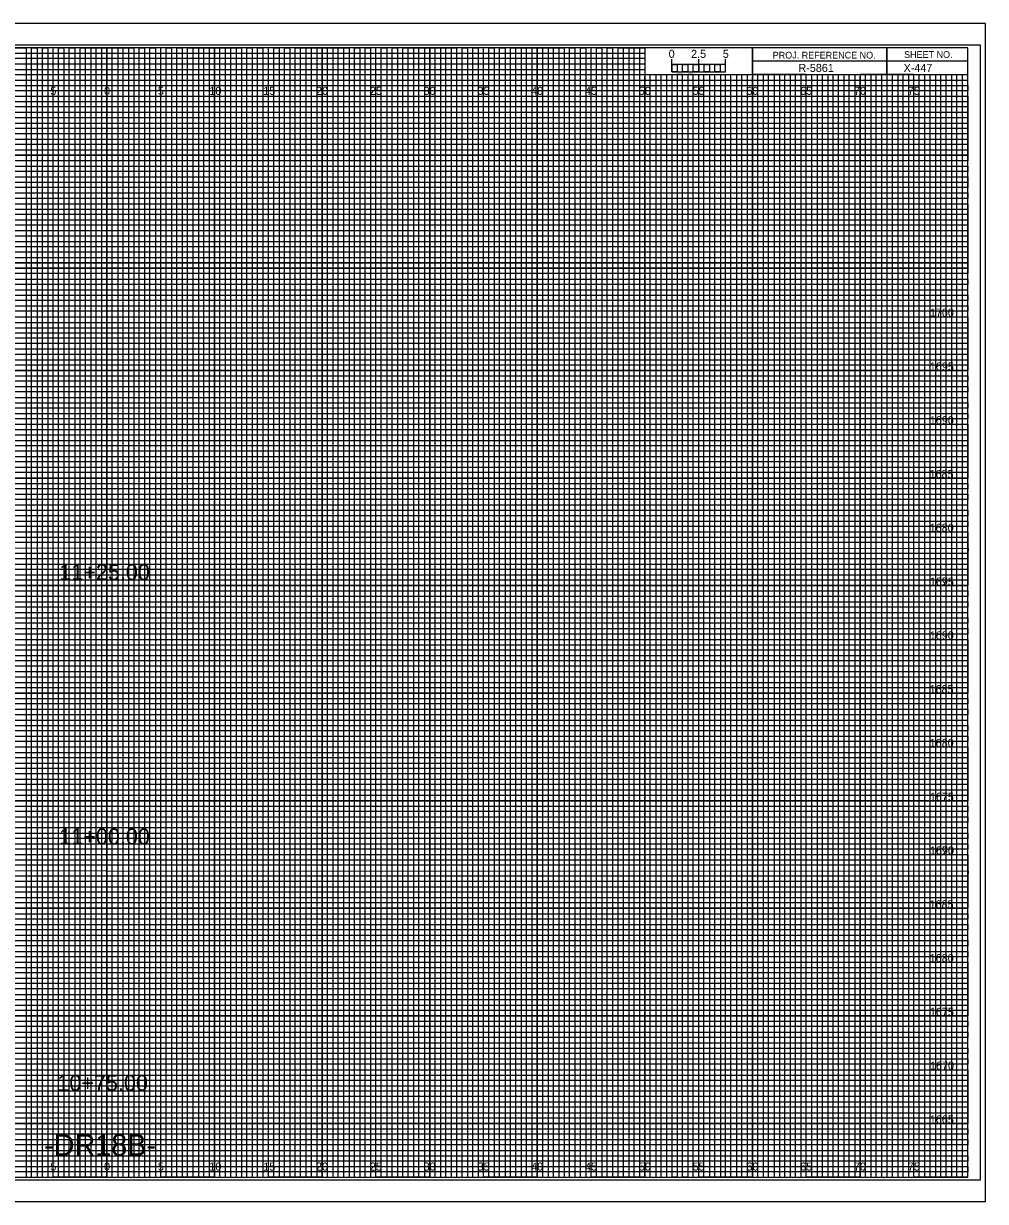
# Model space of a CAD drawing. Extents: x -7 to 162, y -2 to 217.
# Drawn here: x 72.2 to 161.7, y -2.3 to 107.3 of the extents above; entities that cross this region are included whole.
import ezdxf

# ---------------------------------------------------------------- set-up
doc = ezdxf.new("R2010")
doc.units = 0
for name, color, linetype in [('Prop Horizontal Alignment', 7, 'Continuous'), ('Prop XS Alignment Label', 7, 'Continuous'), ('Prop XS Bar Scale Labels', 7, 'Continuous'), ('Prop XS Project Number', 7, 'Continuous'), ('Prop XS Sheet Number', 7, 'Continuous'), ('Raster_Level_0', 7, 'Continuous'), ('Scratch_Level_3', 7, 'Continuous'), ('Sheet Cross Section CELL', 7, 'Continuous'), ('Sheet Cross Section Grid Major CELL', 7, 'Continuous'), ('Sheet Cross Section Grid Middle CELL', 7, 'Continuous'), ('Sheet Cross Section Grid Minor 1 CELL', 7, 'Continuous'), ('Sheet Cross Section Grid Minor 2 CELL', 7, 'Continuous'), ('Sheet Cross Section Scale CELL', 7, 'Continuous'), ('Sheet Cutting Line CELL', 7, 'Continuous'), ('Sheet DOT Grid CELL', 7, 'Continuous'), ('Sheet Plot Border Inside CELL', 7, 'Continuous'), ('Sheet Plot Border Outside CELL', 7, 'Continuous')]:
    doc.layers.add(name, color=color, linetype=linetype)

msp = doc.modelspace()

# ---------------------------------------------------------------- linework, layer by layer
at = {"layer": 'Sheet Cross Section CELL'}
for p, q in [((152.5, 105), (152.5, 102.5)), ((152.5, 102.5), (152.5, 105)), ((160, 103.75), (140, 103.75)), ((140, 103.75), (140, 102.5)), ((140, 102.5), (160, 102.5))]:
    msp.add_line(p, q, dxfattribs=at)
for points in [[(160, 105), (0, 105), (0, 0), (160, 0)], [(140, 105), (130, 105), (130, 102.52), (140, 102.52)], [(160, 105), (140, 105), (140, 102.5), (160, 102.5)]]:
    msp.add_lwpolyline(points, close=True, dxfattribs=at)
at = {"layer": 'Sheet Cross Section Grid Major CELL'}
for p, q in [((75, 105), (70, 105)), ((75, 0), (75, 105)), ((85, 105), (80, 105)), ((80, 105), (80, 0)), ((85, 0), (85, 105)), ((95, 105), (90, 105)), ((90, 105), (90, 0)), ((95, 0), (95, 105)), ((105, 105), (100, 105)), ((100, 105), (100, 0)), ((105, 0), (105, 105)), ((115, 105), (110, 105)), ((110, 105), (110, 0)), ((115, 0), (115, 105)), ((125, 105), (120, 105)), ((120, 105), (120, 0)), ((125, 0), (125, 105)), ((130, 105), (130, 0)), ((135, 0), (135, 102.5)), ((145, 102.5), (140, 102.5)), ((140, 102.5), (140, 0)), ((145, 0), (145, 102.5)), ((155, 102.5), (150, 102.5)), ((150, 102.5), (150, 0)), ((155, 0), (155, 102.5)), ((80, 0), (75, 0)), ((90, 0), (85, 0)), ((100, 0), (95, 0)), ((110, 0), (105, 0)), ((120, 0), (115, 0)), ((130, 0), (125, 0)), ((140, 0), (135, 0)), ((150, 0), (145, 0)), ((160, 0), (155, 0)), ((160, 0), (160, 0))]:
    msp.add_line(p, q, dxfattribs=at)
for points in [[(0, 100), (160, 100), (160, 95), (0, 95)], [(0, 90), (160, 90), (160, 85), (0, 85)], [(0, 80), (160, 80), (160, 75), (0, 75)], [(0, 70), (160, 70), (160, 65), (0, 65)], [(0, 60), (160, 60), (160, 55), (0, 55)], [(0, 50), (160, 50), (160, 45), (0, 45)], [(0, 40), (160, 40), (160, 35), (0, 35)], [(0, 30), (160, 30), (160, 25), (0, 25)], [(0, 20), (160, 20), (160, 15), (0, 15)], [(0, 10), (160, 10), (160, 5), (0, 5)]]:
    msp.add_lwpolyline(points, dxfattribs=at)
at = {"layer": 'Sheet Cross Section Grid Middle CELL'}
for points in [[(67.5, 105), (72.5, 105), (72.5, 0), (77.5, 0), (77.5, 105), (82.5, 105), (82.5, 0), (87.5, 0), (87.5, 105), (92.5, 105), (92.5, 0), (97.5, 0), (97.5, 105), (102.5, 105), (102.5, 0), (107.5, 0), (107.5, 105), (112.5, 105), (112.5, 0), (117.5, 0), (117.5, 105), (122.5, 105), (122.5, 0), (127.5, 0), (127.5, 105), (129.97, 105), (130, 105), (130, 102.5), (132.5, 102.5), (132.5, 0), (137.5, 0), (137.5, 102.5), (142.5, 102.5), (142.5, 0), (147.5, 0), (147.5, 102.5), (152.5, 102.5), (152.5, 0), (157.5, 0), (157.5, 102.5)], [(0, 102.5), (137.5, 102.5)], [(0, 92.5), (160, 92.5), (160, 97.5), (0, 97.5)], [(0, 82.5), (160, 82.5), (160, 87.5), (0, 87.5)], [(0, 72.5), (160, 72.5), (160, 77.5), (0, 77.5)], [(0, 62.5), (160, 62.5), (160, 67.5), (0, 67.5)], [(0, 52.5), (160, 52.5), (160, 57.5), (0, 57.5)], [(0, 42.5), (160, 42.5), (160, 47.5), (0, 47.5)], [(0, 32.5), (160, 32.5), (160, 37.5), (0, 37.5)], [(0, 22.5), (160, 22.5), (160, 27.5), (0, 27.5)], [(0, 12.5), (160, 12.5), (160, 17.5), (0, 17.5)], [(0, 2.5), (160, 2.5), (160, 7.5), (0, 7.5)]]:
    msp.add_lwpolyline(points, dxfattribs=at)
at = {"layer": 'Sheet Cross Section Grid Minor 1 CELL'}
for p, q in [((0, 104.5), (130, 104.5)), ((130, 104.5), (130, 103.99)), ((130, 103.99), (0, 103.99)), ((0, 103.5), (130, 103.5)), ((130, 102.95), (0, 102.95)), ((130, 103.5), (130, 102.95)), ((0, 102), (160, 102))]:
    msp.add_line(p, q, dxfattribs=at)
for points in [[(0, 101.5), (135, 101.5), (160, 101.5), (160, 101), (0, 101)], [(0, 100.5), (160, 100.5), (160, 99.5), (0, 99.5)], [(0, 99), (160, 99), (160, 98.5), (0, 98.49)], [(0, 98), (160, 98), (160, 97), (0, 97)], [(0, 96.5), (160, 96.5), (160, 96), (0, 96)], [(0, 95.5), (160, 95.5), (160, 94.5), (0, 94.5)], [(0, 94), (160, 94), (160, 93.5), (0, 93.5)], [(0, 93), (160, 93), (160, 92), (0, 92)], [(0, 91.5), (160, 91.5), (160, 91), (0, 91)], [(0, 90.5), (160, 90.5), (160, 89.5), (0, 89.5)], [(0, 89), (160, 89), (160, 88.5), (0, 88.5)], [(0, 88), (160, 88), (160, 86.98), (160, 86.5), (160, 86), (0, 86)], [(0, 87), (160, 87), (160, 86.5), (0, 86.5)], [(0, 85.5), (160, 85.5), (160, 84.5), (0, 84.52)], [(0, 84.52), (160, 84.5), (160, 84), (0, 84)], [(0, 83.5), (160, 83.5), (160, 83), (0, 83)], [(0, 82), (160, 82), (160, 81.5), (0, 81.5)], [(0, 81), (160, 81), (160, 80.5), (0, 80.5)], [(-0.04, 79.45), (160, 79.45), (160, 78.94), (-0.04, 78.94)], [(0, 78.5), (160, 78.5), (160, 78), (0, 78)], [(0, 77), (160, 77), (160, 76.5), (0, 76.5)], [(0, 76), (160, 76), (160, 75.5), (0, 75.5)], [(0, 74.5), (160, 74.5), (160, 74), (0, 74)], [(0, 73.5), (160, 73.5), (160, 73), (0, 73)], [(0, 72), (160, 72), (160, 71.5), (0, 71.5)], [(0, 71), (160, 71), (160, 70.5), (0, 70.5)], [(0, 69.5), (160, 69.5), (160, 68.99), (0, 69)], [(0, 68.5), (160, 68.5), (160, 68), (0, 68)], [(0, 67), (160, 67), (160, 66.5), (0, 66.5)], [(0, 66), (160, 66), (160, 65.5), (0, 65.5)], [(0, 64.5), (160, 64.5), (160, 64), (0, 64)], [(0, 63.5), (160, 63.5), (160, 63), (0, 63)], [(0, 62), (160, 62), (160, 61.5), (0, 61.5)], [(0, 61), (160, 61), (160, 60.5), (0, 60.5)], [(0, 59.5), (160, 59.5), (160, 59), (0, 59)], [(0, 58.5), (160.03, 58.45), (160, 58), (0, 58)], [(0, 57), (160, 57), (160, 56.5), (0, 56.5)], [(0, 56), (160, 56), (160, 55.5), (0, 55.5)], [(0, 54.5), (160, 54.5), (160, 54), (0, 54)], [(0, 53.5), (160, 53.5), (160, 53), (0, 53)], [(0, 52), (160, 52), (160, 51.5), (0, 51.5)], [(0, 51), (160, 51), (160, 50.5), (0, 50.5)], [(0, 49.5), (160, 49.5), (160, 49), (0, 49)], [(0, 48.5), (160, 48.5), (160, 48), (0, 48)], [(0, 47), (160, 47), (160, 46.5), (0, 46.5)], [(0, 46), (160, 46), (160, 45.5), (0, 45.5)], [(0, 44.5), (160, 44.5), (160, 44), (0, 44)], [(0, 43.5), (160, 43.5), (160, 43), (0, 43)], [(0, 42), (160, 42), (160, 41.5), (0, 41.5)], [(0, 41), (160, 41), (160, 40.5), (0, 40.5)], [(0, 39.5), (160, 39.5), (160, 38.99), (0, 39)], [(0, 38.5), (160, 38.5), (160, 38), (0, 38)], [(0, 37), (160, 37), (160, 36.5), (0, 36.5)], [(0, 36), (160, 36), (160, 35.5), (0, 35.5)], [(0, 34.5), (160, 34.5), (160, 34), (0, 34)], [(0, 33.5), (160, 33.5), (160, 33), (0, 33)], [(0, 32), (160, 32), (160, 31.5), (0, 31.5)], [(0, 31), (160, 31), (160, 30.5), (0, 30.5)], [(0, 29.5), (160, 29.5), (160, 29), (0, 29)], [(0, 28.5), (160.03, 28.46), (160, 28), (0, 28)], [(0, 27), (160, 27), (160, 26.5), (0, 26.5)], [(0, 26), (160, 26), (160, 25.5), (0, 25.5)], [(0, 24.5), (160, 24.5), (160, 24), (0, 24)], [(0, 23.5), (160, 23.5), (160, 23), (0, 23)], [(0, 22), (160, 22), (160, 21.5), (0, 21.5)], [(0, 21), (160, 21), (160, 20.5), (0, 20.5)], [(0, 19.5), (160, 19.5), (160, 19), (0, 19)], [(0, 18.5), (160, 18.5), (160, 18), (0, 18)], [(0, 17), (160, 17), (160, 16.5), (0, 16.5)], [(0, 16), (160, 16), (160, 15.5), (0, 15.5)], [(0, 14.5), (160, 14.5), (160, 14), (0, 14)], [(0, 13.5), (160, 13.5), (160, 13), (0, 13)], [(0, 12), (160, 12), (160, 11.5), (0, 11.5)], [(0, 11), (160, 11), (160, 10.5), (0, 10.5)], [(0, 9.5), (160, 9.5), (160, 9), (0, 9)], [(0, 8.5), (160, 8.5), (160, 8), (0, 8)], [(0, 7), (160, 7), (160, 6.5), (0, 6.5)], [(0, 6), (160, 6), (160, 5.5), (0, 5.5)], [(0, 4.5), (160, 4.5), (160, 4), (0, 4)], [(0, 3.5), (160, 3.5), (160, 3), (0, 3)], [(0, 2), (160, 2), (160, 1.5), (0, 1.5)], [(0, 1), (160, 1), (160, 0.5), (0, 0.5)]]:
    msp.add_lwpolyline(points, dxfattribs=at)
at = {"layer": 'Sheet Cross Section Grid Minor 2 CELL'}
for p, q in [((133.5, 102.5), (133, 102.5)), ((133, 102.5), (133, 0)), ((133.5, 0), (133.5, 102.5)), ((134.5, 102.5), (134, 102.5)), ((134, 102.5), (134, 0)), ((134.5, 0), (134.5, 102.5)), ((133, 0), (132.5, 0)), ((134, 0), (133.5, 0))]:
    msp.add_line(p, q, dxfattribs=at)
for points in [[(72.5, 0), (73, 0), (73, 105), (73.5, 105), (73.5, 0)], [(73.5, 0), (74, 0), (74, 105), (74.5, 105), (74.5, 0)], [(75, 0), (75.5, 0), (75.5, 105), (76, 105), (76, 0)], [(76, 0), (76.5, 0), (76.5, 105), (77, 105), (77, 0)], [(77.5, 0), (78, 0), (78, 105), (78.5, 105), (78.5, 0)], [(78.5, 0), (79, 0), (79, 105), (79.5, 105), (79.5, 0)], [(80, 0), (80.5, 0), (80.5, 105), (81, 105), (81, 0)], [(81, 0), (81.5, 0), (81.5, 105), (82, 105), (82, 0)], [(82.5, 0), (83, 0), (83, 105), (83.5, 105), (83.5, 0)], [(83.5, 0), (84, 0), (84, 105), (84.5, 105), (84.5, 0)], [(85, 0), (85.5, 0), (85.5, 105), (86, 105), (86, 0)], [(86, 0), (86.5, 0), (86.5, 105), (87, 105), (87, 0)], [(87.5, 0), (88, 0), (88, 105), (88.5, 105), (88.5, 0)], [(88.5, 0), (89, 0), (89, 105), (89.5, 105), (89.5, 0)], [(90, 0), (90.5, 0), (90.5, 105), (91, 105), (91, 0)], [(91, 0), (91.5, 0), (91.5, 105), (92, 105), (92, 0)], [(92.5, 0), (93, 0), (93, 105), (93.5, 105), (93.5, 0)], [(93.5, 0), (94, 0), (94, 105), (94.5, 105), (94.5, 0)], [(95, 0), (95.5, 0), (95.5, 105), (96, 105), (96, 0)], [(96, 0), (96.5, 0), (96.5, 105), (97, 105), (97, 0)], [(97.5, 0), (98, 0), (98, 105), (98.5, 105), (98.5, 0)], [(98.5, 0), (99, 0), (99, 105), (99.5, 105), (99.5, 0)], [(100, 0), (100.5, 0), (100.5, 105), (101, 105), (101, 0)], [(101, 0), (101.5, 0), (101.5, 105), (102, 105), (102, 0)], [(102.5, 0), (103, 0), (103, 105), (103.5, 105), (103.5, 0)], [(103.5, 0), (104, 0), (104, 105), (104.5, 105), (104.5, 0)], [(105, 0), (105.5, 0), (105.5, 105), (106, 105), (106, 0)], [(106, 0), (106.5, 0), (106.5, 105), (107, 105), (107, 0)], [(107.5, 0), (108, 0), (108, 105), (108.5, 105), (108.5, 0)], [(108.5, 0), (109, 0), (109, 105), (109.5, 105), (109.5, 0)], [(110, 0), (110.5, 0), (110.5, 105), (111, 105), (111, 0)], [(111, 0), (111.5, 0), (111.5, 105), (112, 105), (112, 0)], [(112.5, 0), (113, 0), (113, 105), (113.5, 105), (113.5, 0)], [(113.5, 0), (114, 0), (114, 105), (114.5, 105), (114.5, 0)], [(115, 0), (115.5, 0), (115.5, 105), (116, 105), (116, 0)], [(116, 0), (116.5, 0), (116.5, 105), (117, 105), (117, 0)], [(117.5, 0), (118, 0), (118, 105), (118.5, 105), (118.5, 0)], [(118.5, 0), (119, 0), (119, 105), (119.5, 105), (119.5, 0)], [(120, 0), (120.5, 0), (120.5, 105), (121, 105), (121, 0)], [(121, 0), (121.5, 0), (121.5, 105), (122, 105), (122, 0)], [(122.5, 0), (123, 0), (123, 105), (123.5, 105), (123.5, 0)], [(123.5, 0), (124, 0), (124, 105), (124.5, 105), (124.5, 0)], [(125, 0), (125.5, 0), (125.5, 105), (126, 105), (126, 0)], [(126, 0), (126.5, 0), (126.5, 105), (127, 105), (127, 0)], [(127.5, 0), (128, 0), (128, 105), (128.5, 105), (128.5, 0)], [(128.5, 0), (129, 0), (129, 105), (129.5, 105), (129.5, 0)], [(130, 0), (130.5, 0), (130.5, 102.5), (131.01, 102.5), (131.01, 0)], [(131, 0), (131.5, 0), (131.5, 102.5), (132, 102.5), (132, 0)], [(135, 0), (135.49, 0), (135.49, 102.5), (136, 102.5), (136, 0)], [(136, 0), (136.5, 0), (136.5, 102.5), (137.03, 102.5), (137.03, 0)], [(137.5, 0), (138, 0), (138, 102.5), (138.5, 102.5), (138.5, 0)], [(138.5, 0), (139, 0), (139, 102.5), (139.5, 102.5), (139.5, 0)], [(140, 0), (140.5, 0), (140.5, 102.5), (141, 102.5), (141, 0)], [(141, 0), (141.5, 0), (141.5, 102.5), (142, 102.5), (142, 0)], [(142.5, 0), (143, 0), (143, 102.5), (143.5, 102.5), (143.5, 0)], [(143.5, 0), (144, 0), (144, 102.5), (144.5, 102.5), (144.5, 0)], [(145, 0), (145.5, 0), (145.5, 102.5), (146, 102.5), (146, 0)], [(146, 0), (146.5, 0), (146.5, 102.5), (147, 102.5), (147, 0)], [(147.5, 0), (148, 0), (148, 102.5), (148.5, 102.5), (148.5, 0)], [(148.5, 0), (149, 0), (149, 102.5), (149.5, 102.5), (149.5, 0)], [(150, 0), (150.5, 0), (150.5, 102.5), (151, 102.5), (151, 0)], [(151, 0), (151.5, 0), (151.5, 102.5), (152, 102.5), (152, 0)], [(152.5, 0), (153, 0), (153, 102.5), (153.5, 102.5), (153.5, 0)], [(153.5, 0), (154, 0), (154, 102.5), (154.5, 102.5), (154.5, 0)], [(155, 0), (155.5, 0), (155.5, 102.5), (156, 102.5), (156, 0)], [(156, 0), (156.5, 0), (156.5, 102.5), (157, 102.5), (157, 0)], [(157.5, 0), (158, 0), (158, 102.5), (158.5, 102.5), (158.5, 0)], [(158.5, 0), (159, 0), (159, 102.5), (159.5, 102.5), (159.5, 0)]]:
    msp.add_lwpolyline(points, dxfattribs=at)
at = {"layer": 'Sheet Cross Section Scale CELL'}
for p, q in [((132.5, 102.75), (132.5, 103.95)), ((132.5, 103.45), (132.5, 103.95)), ((135, 102.75), (135, 103.95)), ((137.5, 102.75), (137.5, 103.95)), ((137.5, 103.45), (137.5, 103.95))]:
    msp.add_line(p, q, dxfattribs=at)
for points in [[(137.5, 103.45), (132.5, 103.45), (132.5, 102.75), (137.5, 102.75)], [(132.5, 103.45), (133, 103.45), (133, 102.75), (132.5, 102.75)], [(133.5, 103.45), (134, 103.45), (134, 102.75), (133.5, 102.75)], [(134.5, 103.45), (135, 103.45), (135, 102.75), (134.5, 102.75)], [(135.5, 103.45), (136, 103.45), (136, 102.75), (135.5, 102.75)], [(136.5, 103.45), (137, 103.45), (137, 102.75), (136.5, 102.75)]]:
    msp.add_lwpolyline(points, close=True, dxfattribs=at)
at = {"layer": 'Sheet Cutting Line CELL'}
for p, q in [((161.65, 107.25), (-6.7, 107.25)), ((-6.7, -2.25), (161.65, -2.25))]:
    msp.add_line(p, q, dxfattribs=at)
at = {"layer": 'Sheet DOT Grid CELL'}
for p, q in [((75, 0), (75, 105)), ((80, 0), (80, 105)), ((85, 0), (85, 105)), ((90, 0), (90, 105)), ((95, 0), (95, 105)), ((100, 0), (100, 105)), ((105, 0), (105, 105)), ((110, 0), (110, 105)), ((115, 0), (115, 105)), ((120, 0), (120, 105)), ((125, 0), (125, 105)), ((130, 0), (130, 102.34)), ((135, 0), (135, 102.34)), ((140, 0), (140, 102.34)), ((145, 0), (145, 102.34)), ((150, 0), (150, 102.34)), ((155, 0), (155, 102.34)), ((0, 100), (160, 100)), ((0, 95), (160, 95)), ((0, 90), (160, 90)), ((0, 85), (160, 85)), ((0, 80), (160, 80)), ((0, 75), (160, 75)), ((0, 70), (160, 70)), ((0, 65), (160, 65)), ((0, 60), (160, 60)), ((0, 55), (160, 55)), ((0, 50), (160, 50)), ((0, 45), (160, 45)), ((0, 40), (160, 40)), ((0, 35), (160, 35)), ((0, 30), (160, 30)), ((0, 25), (160, 25)), ((0, 20), (160, 20)), ((0, 15), (160, 15)), ((0, 10), (160, 10)), ((0, 5), (160, 5))]:
    msp.add_line(p, q, dxfattribs=at)
at = {"layer": 'Sheet Plot Border Inside CELL'}
msp.add_lwpolyline([(-5.4, -0.25), (161.2, -0.25), (161.2, 105.25), (-5.4, 105.25)], close=True, dxfattribs=at)
at = {"layer": 'Sheet Plot Border Outside CELL'}
msp.add_lwpolyline([(-6.7, -2.25), (161.65, -2.25), (161.65, 107.25), (-6.7, 107.25)], close=True, dxfattribs=at)

# ---------------------------------------------------------------- texts
at = {"layer": 'Prop Horizontal Alignment'}
for s, p in [('11+25.00', (75.57, 55.5)), ('11+00.00', (75.57, 30.93)), ('10+75.00', (75.39, 8.02))]:
    msp.add_text(s, height=1.5, dxfattribs=at).set_placement(p)
at = {"layer": 'Prop XS Alignment Label'}
msp.add_text('-DR18B-', height=2, dxfattribs=at).set_placement((74.16, 2))
at = {"layer": 'Prop XS Bar Scale Labels'}
for s, p in [('2.5', (134.29, 104.06)), ('5', (137.24, 104.06))]:
    msp.add_text(s, height=0.75, dxfattribs=at).set_placement(p)
at = {"layer": 'Prop XS Project Number'}
msp.add_text('R-5861', height=0.75, dxfattribs=at).set_placement((144.27, 102.75))
at = {"layer": 'Prop XS Sheet Number'}
msp.add_text('X-447', height=0.75, dxfattribs=at).set_placement((154.04, 102.75))
at = {"layer": 'Raster_Level_0'}
for s, p in [('5', (74.74, 100.62)), ('0', (79.73, 100.62)), ('0', (79.73, 100.62)), ('5', (84.74, 100.62)), ('10', (89.52, 100.62)), ('15', (94.53, 100.62)), ('20', (99.43, 100.62)), ('25', (104.44, 100.62)), ('30', (109.43, 100.62)), ('35', (114.44, 100.62)), ('40', (119.43, 100.62)), ('45', (124.44, 100.62)), ('50', (129.43, 100.62)), ('55', (134.44, 100.62)), ('60', (139.43, 100.62)), ('65', (144.44, 100.62)), ('70', (149.43, 100.62)), ('75', (154.44, 100.62)), ('5', (74.74, 0.62)), ('0', (79.73, 0.62)), ('0', (79.73, 0.62)), ('5', (84.74, 0.62)), ('10', (89.52, 0.62)), ('15', (94.53, 0.62)), ('20', (99.43, 0.62)), ('25', (104.44, 0.62)), ('30', (109.43, 0.62)), ('35', (114.44, 0.62)), ('40', (119.43, 0.62)), ('45', (124.44, 0.62)), ('50', (129.43, 0.62)), ('55', (134.44, 0.62)), ('60', (139.43, 0.62)), ('65', (144.44, 0.62)), ('70', (149.43, 0.62)), ('75', (154.44, 0.62))]:
    msp.add_text(s, height=0.75, dxfattribs=at).set_placement(p)
at = {"layer": 'Scratch_Level_3'}
for s, p in [('1700', (156.49, 80)), ('1695', (156.48, 75)), ('1690', (156.48, 70)), ('1685', (156.46, 65)), ('1680', (156.47, 60)), ('1695', (156.48, 55)), ('1675', (156.49, 55)), ('1690', (156.48, 50)), ('1685', (156.46, 45)), ('1680', (156.47, 40)), ('1675', (156.49, 35)), ('1690', (156.48, 30)), ('1670', (156.5, 30)), ('1685', (156.46, 25)), ('1680', (156.47, 20)), ('1675', (156.49, 15)), ('1670', (156.5, 10)), ('1665', (156.48, 5))]:
    msp.add_text(s, height=0.75, dxfattribs=at).set_placement(p)
at = {"layer": 'Sheet Cross Section CELL'}
for s, p in [('PROJ. REFERENCE NO.', (141.88, 104)), ('SHEET NO.', (154.09, 104.06))]:
    msp.add_text(s, height=0.625, dxfattribs=at).set_placement(p)
at = {"layer": 'Sheet Cross Section Scale CELL'}
msp.add_text('0', height=0.75, dxfattribs=at).set_placement((132.21, 104.06))

doc.saveas('drawing.dxf')
